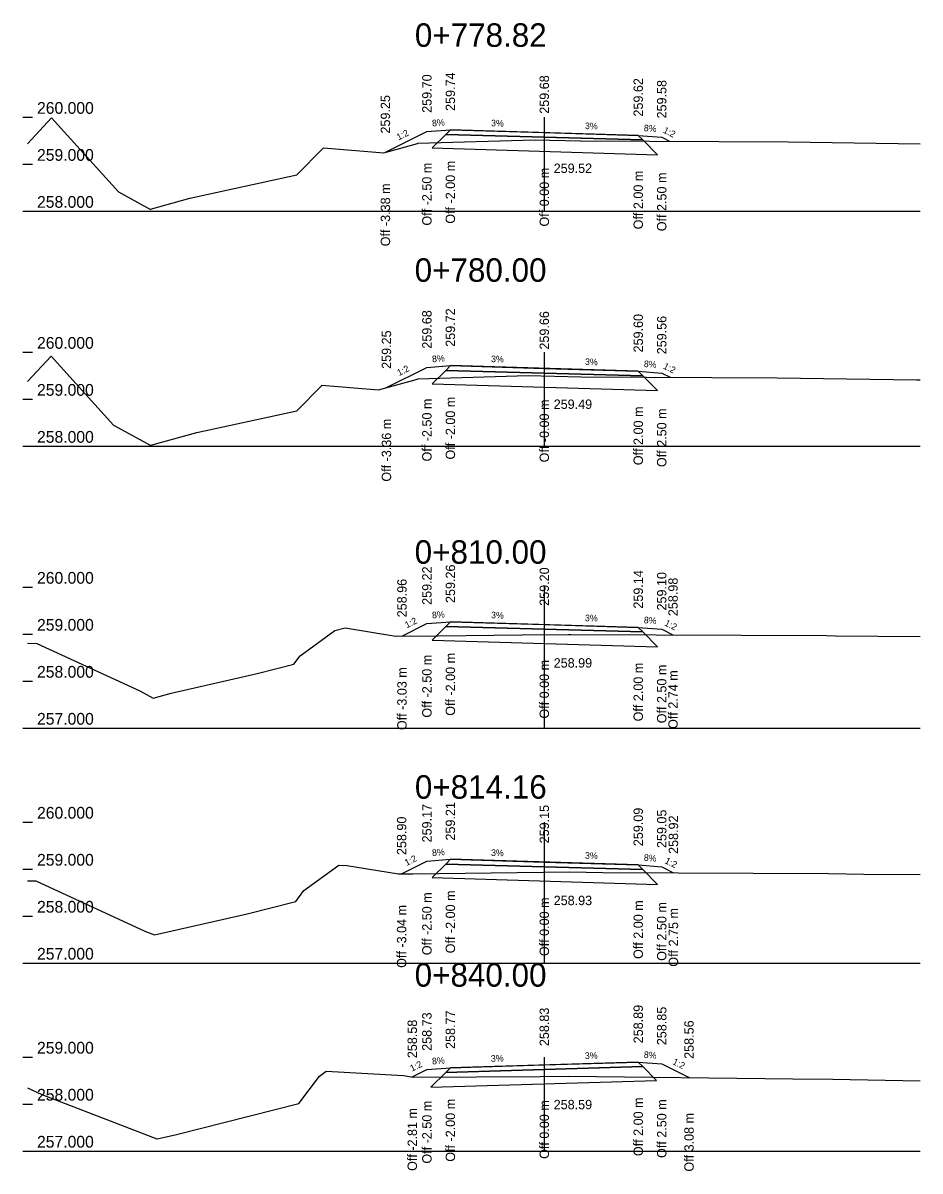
# Model space of a CAD drawing. Extents: x -550605 to -538780, y -1102367 to -1093705.
# Drawn here: x -541268.9 to -541249.8, y -1098197.98 to -1098173.55 of the extents above; entities that cross this region are included whole.
import ezdxf

# ---------------------------------------------------------------- set-up
doc = ezdxf.new("R2010")
doc.units = 0
for name, color, linetype in [('PŘ - offsety od osy', 7, 'Continuous'), ('PŘ - popis', 7, 'Continuous'), ('PŘ - příčné sklony', 7, 'Continuous'), ('PŘ - terén', 7, 'Continuous'), ('PŘ - vozovka', 7, 'Continuous'), ('PŘ - výšky offsetů', 7, 'Continuous')]:
    doc.layers.add(name, color=color, linetype=linetype)

msp = doc.modelspace()

# ---------------------------------------------------------------- linework, layer by layer
at = {"layer": 'PŘ - popis'}
for p, q in [((-541268.898, -1098175.553), (-541268.698, -1098175.553)), ((-541257.798, -1098175.553), (-541257.798, -1098177.553)), ((-541268.898, -1098176.553), (-541268.698, -1098176.553)), ((-541268.898, -1098177.553), (-541268.698, -1098177.553)), ((-541268.798, -1098177.553), (-541249.798, -1098177.553)), ((-541268.898, -1098180.553), (-541268.698, -1098180.553)), ((-541257.798, -1098180.553), (-541257.798, -1098182.553)), ((-541268.898, -1098181.553), (-541268.698, -1098181.553)), ((-541268.898, -1098182.553), (-541268.698, -1098182.553)), ((-541268.798, -1098182.553), (-541249.798, -1098182.553)), ((-541268.898, -1098185.553), (-541268.698, -1098185.553)), ((-541257.798, -1098185.553), (-541257.798, -1098188.553)), ((-541268.898, -1098186.553), (-541268.698, -1098186.553)), ((-541268.898, -1098187.553), (-541268.698, -1098187.553)), ((-541268.898, -1098188.553), (-541268.698, -1098188.553)), ((-541268.798, -1098188.553), (-541249.798, -1098188.553)), ((-541268.898, -1098190.553), (-541268.698, -1098190.553)), ((-541257.798, -1098190.553), (-541257.798, -1098193.553)), ((-541268.898, -1098191.553), (-541268.698, -1098191.553)), ((-541268.898, -1098192.553), (-541268.698, -1098192.553)), ((-541268.898, -1098193.553), (-541268.698, -1098193.553)), ((-541268.798, -1098193.553), (-541249.798, -1098193.553)), ((-541268.898, -1098195.553), (-541268.698, -1098195.553)), ((-541257.798, -1098195.553), (-541257.798, -1098197.553)), ((-541268.898, -1098196.553), (-541268.698, -1098196.553)), ((-541268.898, -1098197.553), (-541268.698, -1098197.553)), ((-541268.798, -1098197.553), (-541249.798, -1098197.553))]:
    msp.add_line(p, q, dxfattribs=at)
at = {"layer": 'PŘ - terén'}
for points in [[(-541268.798, -1098176.119), (-541268.287, -1098175.566), (-541266.865, -1098177.14), (-541266.184, -1098177.513), (-541266.183, -1098177.51), (-541265.342, -1098177.277), (-541263.068, -1098176.78), (-541262.503, -1098176.21), (-541262.498, -1098176.202), (-541261.213, -1098176.307), (-541260.498, -1098176.11), (-541260.495, -1098176.104), (-541260.494, -1098176.105), (-541257.998, -1098176.032), (-541257.031, -1098176.057), (-541257.03, -1098176.057), (-541252.604, -1098176.075), (-541249.798, -1098176.117)], [(-541268.798, -1098181.174), (-541268.299, -1098180.633), (-541266.971, -1098182.101), (-541266.178, -1098182.536), (-541266.177, -1098182.533), (-541265.196, -1098182.261), (-541263.068, -1098181.797), (-541262.538, -1098181.262), (-541262.534, -1098181.255), (-541261.33, -1098181.353), (-541260.498, -1098181.125), (-541260.495, -1098181.118), (-541260.494, -1098181.118), (-541258.143, -1098181.049), (-541257.023, -1098181.079), (-541257.022, -1098181.079), (-541252.838, -1098181.095), (-541249.871, -1098181.139), (-541249.798, -1098181.14)], [(-541268.798, -1098186.745), (-541268.601, -1098186.748), (-541266.408, -1098187.759), (-541266.128, -1098187.915), (-541266.126, -1098187.915), (-541265.745, -1098187.808), (-541263.909, -1098187.387), (-541263.13, -1098187.19), (-541262.999, -1098187.015), (-541262.257, -1098186.476), (-541262.035, -1098186.416), (-541260.957, -1098186.593), (-541260.955, -1098186.592), (-541260.955, -1098186.59), (-541260.656, -1098186.597), (-541258.274, -1098186.568), (-541258.268, -1098186.568), (-541257.284, -1098186.557), (-541257.23, -1098186.558), (-541251.787, -1098186.583), (-541251.597, -1098186.586), (-541249.798, -1098186.599)], [(-541268.798, -1098191.802), (-541268.624, -1098191.804), (-541266.304, -1098192.874), (-541266.1, -1098192.952), (-541266.098, -1098192.953), (-541266.098, -1098192.953), (-541264.127, -1098192.501), (-541263.09, -1098192.239), (-541262.915, -1098192.006), (-541262.173, -1098191.467), (-541262.002, -1098191.477), (-541260.901, -1098191.652), (-541260.597, -1098191.651), (-541257.258, -1098191.612), (-541256.551, -1098191.621), (-541251.745, -1098191.643), (-541250.992, -1098191.656), (-541249.798, -1098191.665)], [(-541268.798, -1098196.209), (-541268.494, -1098196.35), (-541266.046, -1098197.289), (-541266.046, -1098197.289), (-541266.043, -1098197.293), (-541265.63, -1098197.198), (-541263.025, -1098196.54), (-541262.585, -1098195.955), (-541262.443, -1098195.852), (-541260.793, -1098195.944), (-541260.587, -1098195.977), (-541257.887, -1098195.963), (-541257.281, -1098195.956), (-541252.504, -1098196.017), (-541251.654, -1098196.021), (-541249.798, -1098196.055)]]:
    msp.add_lwpolyline(points, dxfattribs=at)
at = {"layer": 'PŘ - vozovka'}
for points in [[(-541261.181, -1098176.298), (-541260.298, -1098175.857), (-541259.798, -1098175.817), (-541257.798, -1098175.877), (-541255.798, -1098175.937), (-541255.298, -1098175.977), (-541255.121, -1098176.065)], [(-541261.159, -1098181.306), (-541260.298, -1098180.876), (-541259.798, -1098180.836), (-541257.798, -1098180.896), (-541255.798, -1098180.956), (-541255.298, -1098180.996), (-541255.117, -1098181.086)], [(-541260.829, -1098186.593), (-541260.298, -1098186.328), (-541259.798, -1098186.288), (-541257.798, -1098186.348), (-541255.798, -1098186.408), (-541255.298, -1098186.448), (-541255.058, -1098186.568)], [(-541260.836, -1098191.652), (-541260.298, -1098191.383), (-541259.798, -1098191.343), (-541257.798, -1098191.403), (-541255.798, -1098191.463), (-541255.298, -1098191.503), (-541255.049, -1098191.628)], [(-541260.609, -1098195.974), (-541260.298, -1098195.818), (-541259.798, -1098195.778), (-541257.798, -1098195.718), (-541255.798, -1098195.658), (-541255.298, -1098195.698), (-541254.717, -1098195.989)]]:
    msp.add_lwpolyline(points, dxfattribs=at)
for points in [[(-541259.898, -1098175.92), (-541260.187, -1098176.205), (-541255.385, -1098176.349), (-541255.698, -1098176.034)], [(-541259.798, -1098175.817), (-541259.898, -1098175.92), (-541255.698, -1098176.034), (-541255.798, -1098175.937)], [(-541259.798, -1098180.836), (-541259.898, -1098180.939), (-541255.698, -1098181.053), (-541255.798, -1098180.956)], [(-541259.898, -1098180.939), (-541260.187, -1098181.224), (-541255.385, -1098181.369), (-541255.698, -1098181.053)], [(-541259.898, -1098186.391), (-541260.187, -1098186.676), (-541255.385, -1098186.82), (-541255.698, -1098186.505)], [(-541259.798, -1098186.288), (-541259.898, -1098186.391), (-541255.698, -1098186.505), (-541255.798, -1098186.408)], [(-541259.798, -1098191.343), (-541259.898, -1098191.446), (-541255.698, -1098191.56), (-541255.798, -1098191.463)], [(-541259.898, -1098191.446), (-541260.187, -1098191.732), (-541255.385, -1098191.876), (-541255.698, -1098191.56)], [(-541259.898, -1098195.881), (-541260.211, -1098196.191), (-541255.409, -1098196.047), (-541255.698, -1098195.755)], [(-541259.798, -1098195.778), (-541259.898, -1098195.881), (-541255.698, -1098195.755), (-541255.798, -1098195.658)]]:
    msp.add_lwpolyline(points, close=True, dxfattribs=at)

# ---------------------------------------------------------------- texts
at = {"layer": 'PŘ - offsety od osy'}
for s, p in [('Off -2.50 m', (-541260.198, -1098177.857)), ('Off -2.00 m', (-541259.698, -1098177.817)), ('Off 0.00 m', (-541257.698, -1098177.877)), ('Off 2.00 m', (-541255.698, -1098177.937)), ('Off -3.38 m', (-541261.081, -1098178.298)), ('Off 2.50 m', (-541255.198, -1098177.977)), ('Off -2.50 m', (-541260.198, -1098182.876)), ('Off -2.00 m', (-541259.698, -1098182.836)), ('Off -0.00 m', (-541257.698, -1098182.896)), ('Off 2.00 m', (-541255.698, -1098182.956)), ('Off 2.50 m', (-541255.198, -1098182.996)), ('Off -3.36 m', (-541261.059, -1098183.306)), ('Off -2.00 m', (-541259.698, -1098188.288)), ('Off -2.50 m', (-541260.198, -1098188.328)), ('Off 0.00 m', (-541257.698, -1098188.348)), ('Off 2.00 m', (-541255.698, -1098188.408)), ('Off 2.50 m', (-541255.198, -1098188.448)), ('Off -3.03 m', (-541260.729, -1098188.593)), ('Off 2.74 m', (-541254.958, -1098188.568)), ('Off -2.50 m', (-541260.198, -1098193.383)), ('Off -2.00 m', (-541259.698, -1098193.343)), ('Off -3.04 m', (-541260.736, -1098193.652)), ('Off 0.00 m', (-541257.698, -1098193.403)), ('Off 2.00 m', (-541255.698, -1098193.463)), ('Off 2.50 m', (-541255.198, -1098193.503)), ('Off 2.75 m', (-541254.949, -1098193.628)), ('Off -2.50 m', (-541260.198, -1098197.818)), ('Off -2.00 m', (-541259.698, -1098197.778)), ('Off 0.00 m', (-541257.698, -1098197.718)), ('Off 2.00 m', (-541255.698, -1098197.658)), ('Off 2.50 m', (-541255.198, -1098197.698)), ('Off -2.81 m', (-541260.509, -1098197.974)), ('Off 3.08 m', (-541254.617, -1098197.989))]:
    msp.add_text(s, height=0.2, rotation=90, dxfattribs=at).set_placement(p)
at = {"layer": 'PŘ - popis'}
for s, height, p in [('0+778.82', 0.5, (-541260.554, -1098174.053)), ('260.000', 0.25, (-541268.598, -1098175.478)), ('259.000', 0.25, (-541268.598, -1098176.478)), ('258.000', 0.25, (-541268.598, -1098177.478)), ('0+780.00', 0.5, (-541260.558, -1098179.053)), ('260.000', 0.25, (-541268.598, -1098180.478)), ('259.000', 0.25, (-541268.598, -1098181.478)), ('258.000', 0.25, (-541268.598, -1098182.478)), ('0+810.00', 0.5, (-541260.558, -1098185.053)), ('260.000', 0.25, (-541268.598, -1098185.478)), ('259.000', 0.25, (-541268.598, -1098186.478)), ('258.000', 0.25, (-541268.598, -1098187.478)), ('257.000', 0.25, (-541268.598, -1098188.478)), ('0+814.16', 0.5, (-541260.554, -1098190.053)), ('260.000', 0.25, (-541268.598, -1098190.478)), ('259.000', 0.25, (-541268.598, -1098191.478)), ('258.000', 0.25, (-541268.598, -1098192.478)), ('257.000', 0.25, (-541268.598, -1098193.478)), ('0+840.00', 0.5, (-541260.558, -1098194.053)), ('259.000', 0.25, (-541268.598, -1098195.478)), ('258.000', 0.25, (-541268.598, -1098196.478)), ('257.000', 0.25, (-541268.598, -1098197.478))]:
    msp.add_text(s, height=height, dxfattribs=at).set_placement(p)
at = {"layer": 'PŘ - příčné sklony'}
for s, rotation, p in [('8%', 4.5739, (-541260.183, -1098175.748)), ('3%', 358.2816, (-541258.933, -1098175.743)), ('3%', 358.2816, (-541256.933, -1098175.803)), ('8%', 355.4261, (-541255.683, -1098175.846)), ('1:2', 26.5651, (-541260.901, -1098176.047)), ('1:2', 333.4349, (-541255.282, -1098175.873)), ('8%', 4.5739, (-541260.183, -1098180.767)), ('3%', 358.2816, (-541258.933, -1098180.762)), ('1:2', 26.5651, (-541260.89, -1098181.06)), ('3%', 358.2816, (-541256.933, -1098180.822)), ('8%', 355.4261, (-541255.683, -1098180.865)), ('1:2', 333.4349, (-541255.28, -1098180.893)), ('1:2', 26.5651, (-541260.725, -1098186.429)), ('8%', 4.5739, (-541260.183, -1098186.218)), ('3%', 358.2816, (-541258.933, -1098186.214)), ('3%', 358.2816, (-541256.933, -1098186.274)), ('8%', 355.4261, (-541255.683, -1098186.317)), ('1:2', 333.4349, (-541255.25, -1098186.36)), ('8%', 4.5739, (-541260.183, -1098191.274)), ('3%', 358.2816, (-541258.933, -1098191.269)), ('1:2', 26.5651, (-541260.729, -1098191.487)), ('3%', 358.2816, (-541256.933, -1098191.329)), ('8%', 355.4261, (-541255.683, -1098191.372)), ('1:2', 333.4349, (-541255.246, -1098191.418)), ('3%', 1.7184, (-541258.933, -1098195.652)), ('3%', 1.7184, (-541256.933, -1098195.592)), ('8%', 355.4261, (-541255.683, -1098195.567)), ('1:2', 26.5651, (-541260.615, -1098195.865)), ('8%', 4.5739, (-541260.183, -1098195.709)), ('1:2', 333.4349, (-541255.08, -1098195.696))]:
    msp.add_text(s, height=0.14, rotation=rotation, dxfattribs=at).set_placement(p)
at = {"layer": 'PŘ - výšky offsetů'}
for s, p in [('259.70', (-541260.198, -1098175.457)), ('259.74', (-541259.698, -1098175.417)), ('259.68', (-541257.698, -1098175.477)), ('259.62', (-541255.698, -1098175.537)), ('259.58', (-541255.198, -1098175.577)), ('259.25', (-541261.081, -1098175.898)), ('259.72', (-541259.698, -1098180.436)), ('259.68', (-541260.198, -1098180.476)), ('259.66', (-541257.698, -1098180.496)), ('259.60', (-541255.698, -1098180.556)), ('259.56', (-541255.198, -1098180.596)), ('259.25', (-541261.059, -1098180.906)), ('259.22', (-541260.198, -1098185.928)), ('259.26', (-541259.698, -1098185.888)), ('259.20', (-541257.698, -1098185.948)), ('259.14', (-541255.698, -1098186.008)), ('259.10', (-541255.198, -1098186.048)), ('258.96', (-541260.729, -1098186.193)), ('258.98', (-541254.958, -1098186.168)), ('259.21', (-541259.698, -1098190.943)), ('259.17', (-541260.198, -1098190.983)), ('259.15', (-541257.698, -1098191.003)), ('259.09', (-541255.698, -1098191.063)), ('259.05', (-541255.198, -1098191.103)), ('258.90', (-541260.736, -1098191.252)), ('258.92', (-541254.949, -1098191.228)), ('258.83', (-541257.698, -1098195.318)), ('258.89', (-541255.698, -1098195.258)), ('258.85', (-541255.198, -1098195.298)), ('258.58', (-541260.509, -1098195.574)), ('258.73', (-541260.198, -1098195.418)), ('258.77', (-541259.698, -1098195.378)), ('258.56', (-541254.617, -1098195.589))]:
    msp.add_text(s, height=0.2, rotation=90, dxfattribs=at).set_placement(p)
for s, p in [('259.52', (-541257.598, -1098176.737)), ('259.49', (-541257.598, -1098181.758)), ('258.99', (-541257.598, -1098187.263)), ('258.93', (-541257.598, -1098192.318)), ('258.59', (-541257.598, -1098196.662))]:
    msp.add_text(s, height=0.2, dxfattribs=at).set_placement(p)

doc.saveas('drawing.dxf')
